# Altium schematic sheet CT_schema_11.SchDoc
size 390 x 278 mm
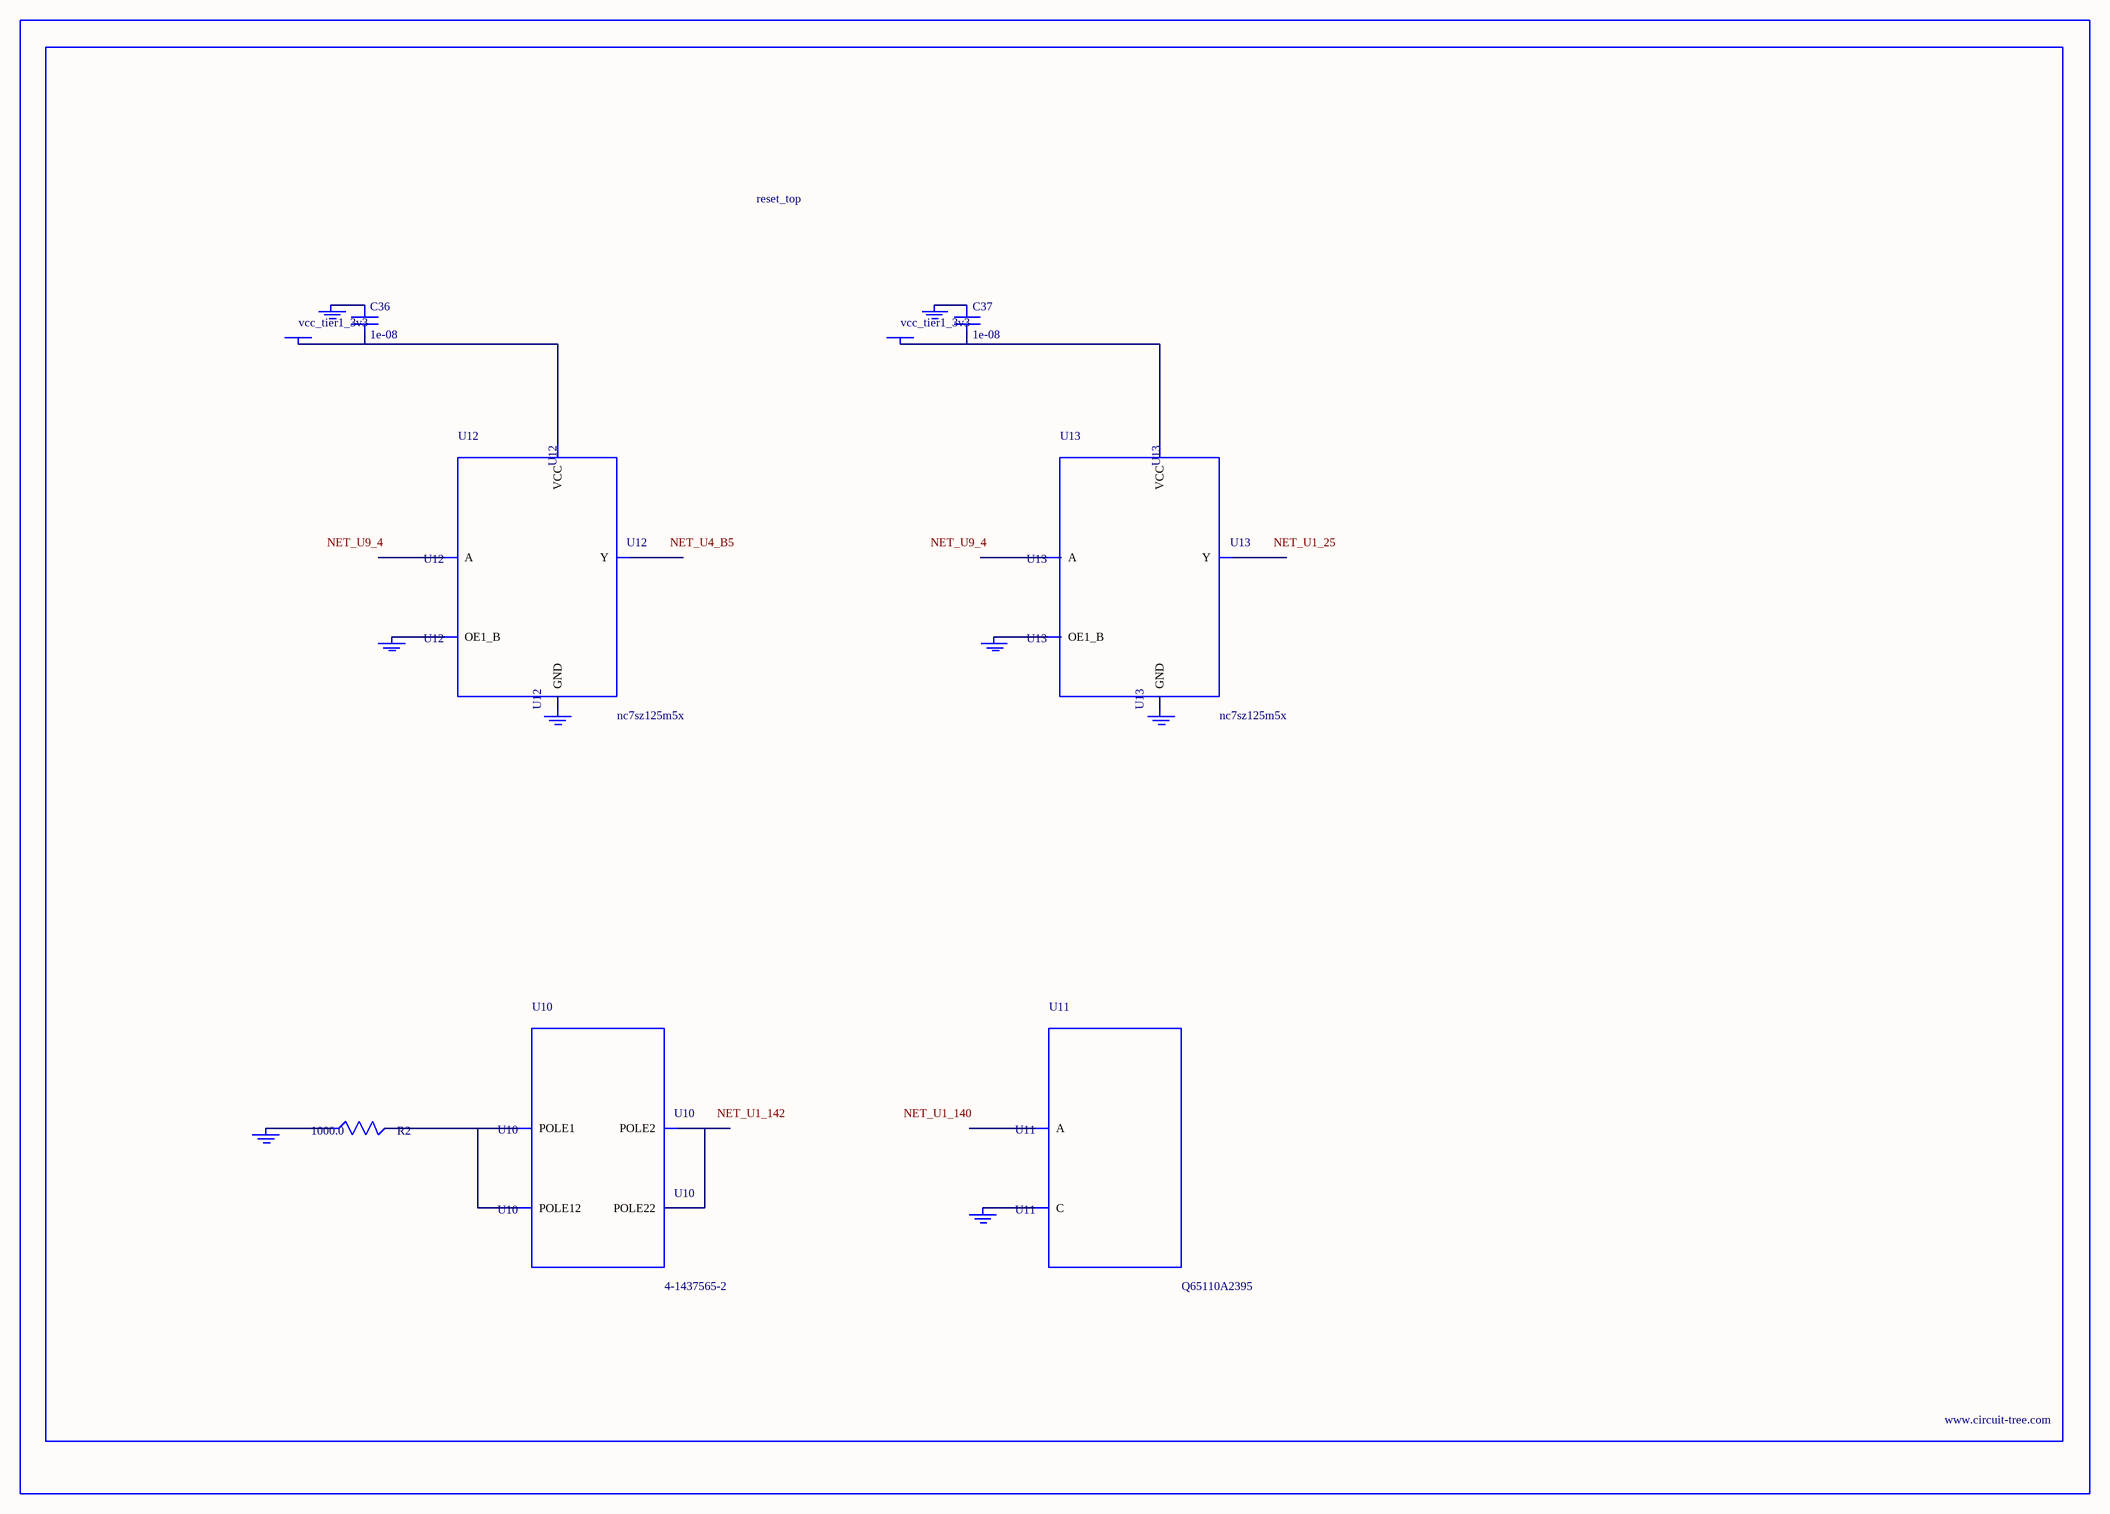
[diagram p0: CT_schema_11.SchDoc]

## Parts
BORDER10  (no value)
C36  1e-08  [C0402]
C37  1e-08  [C0402]
GND_INSTANCE_10_0  (no value)
GND_INSTANCE_10_1  (no value)
GND_INSTANCE_10_2  (no value)
GND_INSTANCE_10_3  (no value)
GND_INSTANCE_10_4  (no value)
GND_INSTANCE_10_5  (no value)
GND_INSTANCE_10_6  (no value)
GND_INSTANCE_10_7  (no value)
POWER_INSTANCE_10_0  vcc_tier1_3v3
POWER_INSTANCE_10_1  vcc_tier1_3v3
R2  1000.0  [R0603]
U10  4-1437565-2  [SW_4-1437565-2]
U11  Q65110A2395  [LGM67K-G1J2-24-Z]
U12  nc7sz125m5x  [NC7SZ125M5X]
U13  nc7sz125m5x  [NC7SZ125M5X]

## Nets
NetC36_1: C36.1 GND_INSTANCE_10_2.0(GND)
NetC36_2: C36.2 POWER_INSTANCE_10_0.0(PWR) U12.5(VCC)
NetC37_1: C37.1 GND_INSTANCE_10_5.0(GND)
NetC37_2: C37.2 POWER_INSTANCE_10_1.0(PWR) U13.5(VCC)
NetGND_INSTANCE_10_0_0: GND_INSTANCE_10_0.0(GND) R2.1
NetGND_INSTANCE_10_1_0: GND_INSTANCE_10_1.0(GND) U11.C
NetGND_INSTANCE_10_3_0: GND_INSTANCE_10_3.0(GND) U12.1(OE1_B)
NetGND_INSTANCE_10_4_0: GND_INSTANCE_10_4.0(GND) U12.3(GND)
NetGND_INSTANCE_10_6_0: GND_INSTANCE_10_6.0(GND) U13.1(OE1_B)
NetGND_INSTANCE_10_7_0: GND_INSTANCE_10_7.0(GND) U13.3(GND)
NetR2_2: R2.2 U10.1(POLE1) U10.2(POLE12)
NetU10_3: U10.3(POLE2) U10.4(POLE22)

Not connected (* = marked no-connect by the designer): U11 A; U12 2(A) 4(Y); U13 2(A) 4(Y)

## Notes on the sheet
- Labels drawn without touching a wire or pin: NET_U1_25, NET_U1_140, NET_U1_142, NET_U4_B5, NET_U9_4

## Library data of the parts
BORDER10 = BORDER_PAGE10
C36 C37 = C0402C103K3RAC
GND_INSTANCE_10_0-GND_INSTANCE_10_7 = GND
POWER_INSTANCE_10_0 POWER_INSTANCE_10_1 = PWR
R2 = RC0603JR-071KL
